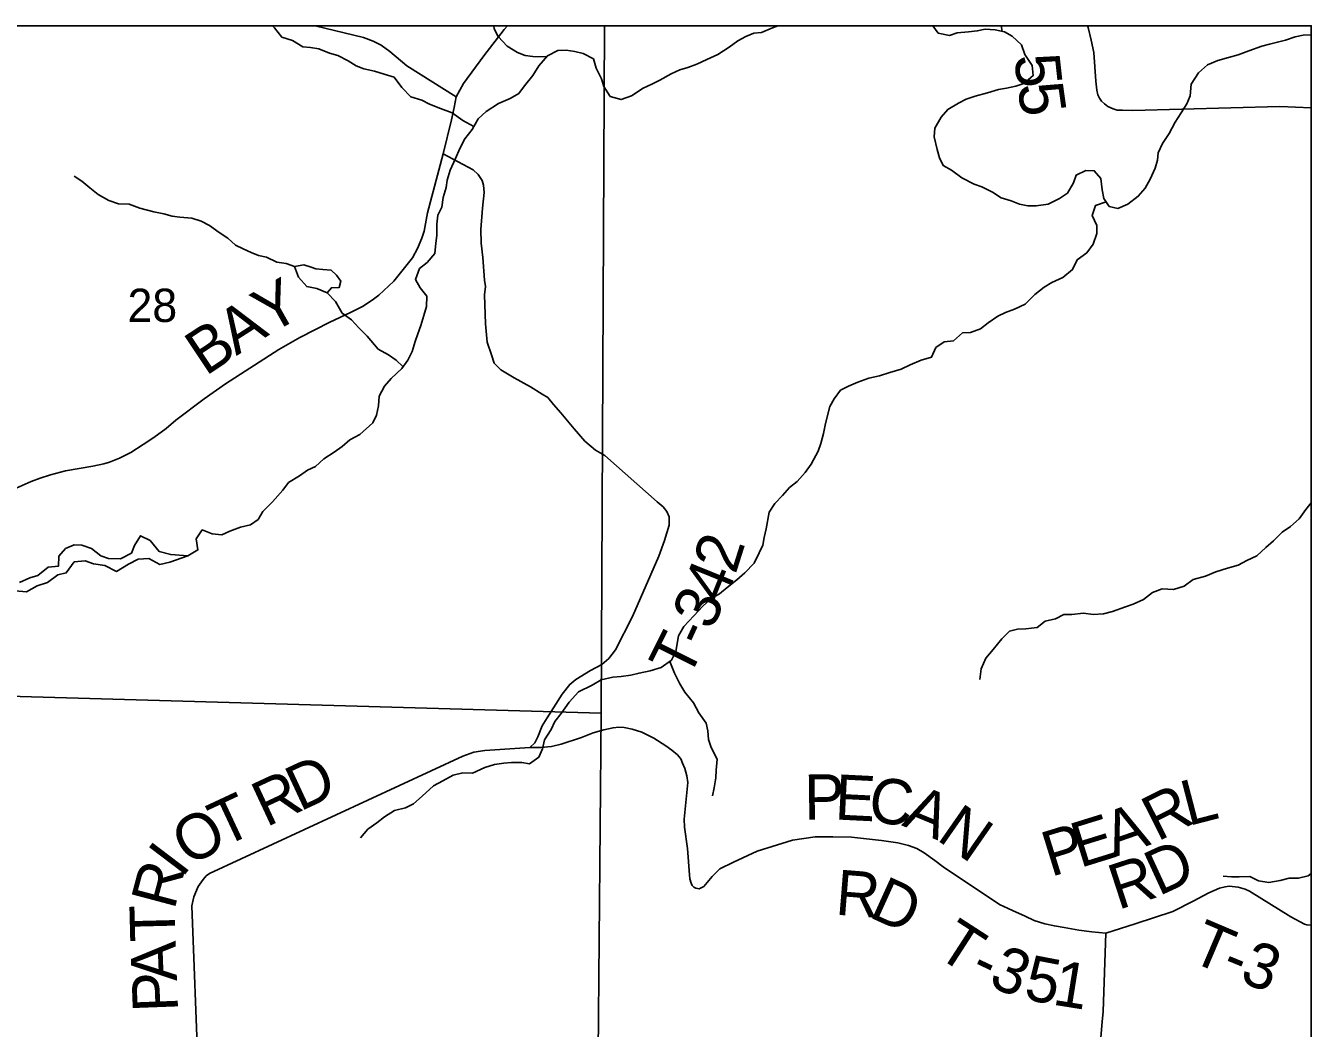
# Model space of a CAD drawing. Extents: x -3.6 to 34, y 0 to 32.8.
# Drawn here: x 1.556 to 3.17, y 31.583 to 32.843 of the extents above; entities that cross this region are included whole.
import ezdxf

# ---------------------------------------------------------------- set-up
doc = ezdxf.new("R2010")
doc.units = 0
for name, color, linetype in [('GM_X_Corporation', 7, 'Continuous'), ('GM_X_County_Road', 7, 'Continuous'), ('GM_X_County_Road_Text', 7, 'Continuous'), ('GM_X_Minor_Lake', 7, 'Continuous'), ('GM_X_Minor_River', 7, 'Continuous'), ('GM_X_Section_Text', 7, 'Continuous'), ('GM_X_Township_Road', 7, 'Continuous'), ('GM_X_Township_Road_Text', 7, 'Continuous'), ('SH_Data', 7, 'Continuous')]:
    doc.layers.add(name, color=color, linetype=linetype)

msp = doc.modelspace()

# ---------------------------------------------------------------- linework, layer by layer
at = {"layer": 'GM_X_Corporation'}
for points in [[(3.1705, 28.9337), (3.1705, 32.8429), (-3.6295, 32.8429), (-3.6295, 26.0429), (2.3706, 26.0429), (2.3712, 26.0804), (2.3716, 26.1248), (2.3732, 26.2253), (2.3789, 26.6097), (2.3911, 27.5117), (2.3952, 27.9336), (2.3997, 28.282), (2.4082, 28.9473), (2.5416, 28.945), (2.5837, 28.9442), (2.8343, 28.9397)], [(3.1705, 30.458), (3.1705, 32.8429), (-3.6295, 32.8429), (-3.6295, 30.6462), (-3.5736, 30.6453), (-2.8007, 30.6338), (-2.7027, 30.634), (-2.3541, 30.6318), (-0.5034, 30.5954), (-0.453, 30.5952), (-0.398, 30.5946), (0.2583, 30.5905), (0.2578, 30.5133), (0.3556, 30.5115), (0.4055, 30.5105), (1.2437, 30.4948), (1.7819, 30.4857), (3.0419, 30.4594)], [(2.2831, 32.8429), (1.2753, 32.8429), (1.2712, 32.0083), (2.2789, 31.9792)], [(1.2712, 32.0083), (2.2789, 31.9792), (2.27, 30.9827), (1.2573, 30.9978)]]:
    msp.add_lwpolyline(points, close=True, dxfattribs=at)
at = {"layer": 'GM_X_County_Road'}
for points in [[(2.1611, 32.8429), (2.1568, 32.838), (2.1315, 32.8052), (2.1059, 32.7701), (2.0966, 32.7534)], [(2.8896, 32.8429), (2.8904, 32.8407), (2.8942, 32.8247), (2.8974, 32.8092), (2.8998, 32.7732), (2.901, 32.7618), (2.9026, 32.7561), (2.9046, 32.7518), (2.9071, 32.7482), (2.9109, 32.7446), (2.9149, 32.7413), (2.9217, 32.7384), (2.9269, 32.7369), (2.9336, 32.7367), (2.9462, 32.7365), (3.131, 32.7413), (3.1705, 32.7399)], [(2.0966, 32.7534), (2.0942, 32.7401), (2.0908, 32.7247), (2.0803, 32.6821)], [(2.0803, 32.6821), (2.0608, 32.6079), (2.0565, 32.5846), (2.0534, 32.576), (2.048, 32.563), (2.042, 32.5513), (2.0185, 32.5219), (1.9995, 32.5042), (1.9914, 32.4979), (1.9792, 32.49), (1.9641, 32.4827), (1.9382, 32.4704), (1.9003, 32.4513), (1.8742, 32.4361), (1.8069, 32.3932), (1.7803, 32.3742), (1.7446, 32.3475), (1.7325, 32.3369), (1.717, 32.3258), (1.7036, 32.3168), (1.6883, 32.3069), (1.6738, 32.2996), (1.6613, 32.2946), (1.6541, 32.2927), (1.6404, 32.2895), (1.6061, 32.2836), (1.5875, 32.2786), (1.5744, 32.2745), (1.5629, 32.2702), (1.5368, 32.2588)]]:
    msp.add_lwpolyline(points, dxfattribs=at)
at = {"layer": 'GM_X_Minor_Lake'}
for points in [[(1.9349, 32.5073), (1.9401, 32.5138), (1.9496, 32.514), (1.9521, 32.522), (1.9463, 32.5295), (1.9397, 32.5358), (1.9295, 32.5368), (1.9204, 32.5374), (1.9146, 32.5396), (1.9055, 32.5425), (1.8937, 32.5404)], [(1.8937, 32.5404), (1.8989, 32.5272), (1.909, 32.5152), (1.9219, 32.5128), (1.9349, 32.5073)]]:
    msp.add_lwpolyline(points, dxfattribs=at)
at = {"layer": 'GM_X_Minor_River'}
msp.add_line((2.7817, 32.8361), (2.7814, 32.8429), dxfattribs=at)
for points in [[(1.7597, 32.177), (1.7725, 32.1844), (1.7704, 32.1984), (1.7778, 32.2095), (1.7904, 32.2048), (1.8026, 32.2035), (1.8124, 32.2078), (1.8259, 32.213), (1.8384, 32.2159), (1.8482, 32.2228), (1.8541, 32.2328), (1.866, 32.2448), (1.8791, 32.2594), (1.8861, 32.269), (1.9, 32.2776), (1.9102, 32.2846), (1.92, 32.2893), (1.9304, 32.2986), (1.9436, 32.3071), (1.9537, 32.3141), (1.9634, 32.3226), (1.9759, 32.3293), (1.9919, 32.344), (1.9967, 32.3535), (1.9992, 32.3653), (2.0001, 32.3775), (2.0067, 32.3901), (2.0149, 32.3997), (2.0284, 32.4121), (2.0362, 32.4228), (2.0413, 32.4335), (2.0453, 32.4461), (2.0485, 32.456), (2.0522, 32.4663), (2.0561, 32.4789), (2.0594, 32.49), (2.0599, 32.5033), (2.0517, 32.5138), (2.0455, 32.5239), (2.0506, 32.5377), (2.0603, 32.5454), (2.07, 32.5566), (2.0713, 32.5695), (2.0723, 32.5794), (2.0724, 32.5934), (2.0738, 32.6048), (2.0789, 32.6148), (2.0806, 32.6269), (2.0842, 32.6395), (2.0855, 32.649), (2.0891, 32.6612), (2.0957, 32.6761), (2.1012, 32.6887), (2.1078, 32.7006), (2.1168, 32.7125), (2.1245, 32.7259), (2.1342, 32.7352), (2.15, 32.7453), (2.1647, 32.7516), (2.1756, 32.7579), (2.1827, 32.7675), (2.1931, 32.7805), (2.2005, 32.7924), (2.2113, 32.8051), (2.2244, 32.8118), (2.2347, 32.8123), (2.2457, 32.8106), (2.256, 32.8081), (2.269, 32.8011), (2.2727, 32.7894), (2.2793, 32.7762), (2.2822, 32.7664), (2.2903, 32.754), (2.3037, 32.7501), (2.3169, 32.7549), (2.3315, 32.7642), (2.3425, 32.7693), (2.3523, 32.7744), (2.3666, 32.7822), (2.3775, 32.7873), (2.3877, 32.7902), (2.399, 32.7945), (2.4114, 32.8004), (2.4254, 32.8067), (2.4397, 32.8157), (2.4502, 32.8238), (2.4603, 32.8293), (2.4705, 32.8336), (2.48, 32.8345), (2.4939, 32.8401), (2.5008, 32.8429)], [(2.1189, 32.7162), (2.1052, 32.7237), (2.0917, 32.7333), (2.0772, 32.7388), (2.0634, 32.7443), (2.0535, 32.7494), (2.0398, 32.7534), (2.0285, 32.7653), (2.0188, 32.7784), (2.0062, 32.782), (1.994, 32.7856), (1.9807, 32.7888), (1.9711, 32.7925), (1.9612, 32.7988), (1.9481, 32.8054), (1.9375, 32.8082), (1.9241, 32.8137), (1.9138, 32.8154), (1.9043, 32.8164), (1.8912, 32.8242), (1.8779, 32.8285), (1.8686, 32.8401), (1.8659, 32.8429)], [(2.21, 32.8036), (2.1931, 32.8041), (2.1832, 32.8054), (2.1736, 32.8091), (2.1606, 32.8172), (2.1494, 32.8291), (2.1446, 32.8389), (2.1439, 32.8429)], [(2.6952, 32.8429), (2.7021, 32.8336), (2.7162, 32.8304), (2.726, 32.834), (2.74, 32.8353), (2.751, 32.8363), (2.7609, 32.8383), (2.7734, 32.8378), (2.7852, 32.8353), (2.7948, 32.8298), (2.8068, 32.819), (2.8108, 32.8065), (2.8201, 32.793), (2.8211, 32.7801), (2.8095, 32.7701), (2.7993, 32.7669), (2.7879, 32.7644), (2.7777, 32.7627), (2.7641, 32.7587), (2.7486, 32.7543), (2.7373, 32.7507), (2.7275, 32.7456), (2.714, 32.7378), (2.7058, 32.7278), (2.6976, 32.714), (2.6971, 32.7033), (2.7007, 32.6875), (2.7036, 32.6769), (2.7083, 32.6671), (2.7187, 32.6612), (2.7317, 32.6519), (2.747, 32.6438), (2.7566, 32.6406), (2.77, 32.6336), (2.7811, 32.6265), (2.7937, 32.623), (2.804, 32.6186), (2.8147, 32.6168), (2.825, 32.6166), (2.8401, 32.6188), (2.8544, 32.6258), (2.8642, 32.6324), (2.8719, 32.6455), (2.8752, 32.655), (2.8872, 32.6609), (2.8979, 32.6607), (2.906, 32.651), (2.9078, 32.6366), (2.9098, 32.626), (2.9168, 32.6159), (2.9275, 32.6134), (2.9403, 32.6185), (2.9531, 32.6286), (2.962, 32.6386), (2.9683, 32.6501), (2.9745, 32.6638), (2.9774, 32.6738), (2.9784, 32.6833), (2.9835, 32.6947), (2.992, 32.7074), (2.9994, 32.7215), (3.0071, 32.7334), (3.0142, 32.7449), (3.0182, 32.7549), (3.0198, 32.7693), (3.0287, 32.7835), (3.0403, 32.7935), (3.0531, 32.7991), (3.0667, 32.8031), (3.0788, 32.8063), (3.092, 32.8111), (3.1083, 32.817), (3.1181, 32.8195), (3.1279, 32.8223), (3.1381, 32.8247), (3.1502, 32.8287), (3.1604, 32.8308), (3.1705, 32.8313)], [(2.0302, 32.4145), (2.0214, 32.4226), (2.0118, 32.4296), (1.9987, 32.4366), (1.9848, 32.4527), (1.9744, 32.4632), (1.9655, 32.4733), (1.9536, 32.4818), (1.9453, 32.4965), (1.9349, 32.5073), (1.9219, 32.5128), (1.909, 32.5152), (1.8989, 32.5272), (1.8937, 32.5404), (1.8834, 32.544), (1.8716, 32.5457), (1.8586, 32.5523), (1.8487, 32.5541), (1.8391, 32.5581), (1.8292, 32.5625), (1.8196, 32.5673), (1.81, 32.5758), (1.7992, 32.5832), (1.7869, 32.5918), (1.7766, 32.5973), (1.7647, 32.6013), (1.7499, 32.6022), (1.74, 32.6035), (1.7297, 32.6064), (1.7172, 32.6092), (1.6996, 32.6135), (1.6862, 32.6186), (1.6726, 32.6191), (1.6607, 32.6235), (1.6473, 32.6308), (1.6369, 32.639), (1.6265, 32.6475), (1.6169, 32.6538)], [(2.9127, 32.6218), (2.8994, 32.6171), (2.8954, 32.6045), (2.9013, 32.5917), (2.9011, 32.5818), (2.8964, 32.5685), (2.8886, 32.5577), (2.8766, 32.5488), (2.8707, 32.5366), (2.8584, 32.5265), (2.8448, 32.5202), (2.835, 32.5144), (2.8234, 32.5051), (2.8111, 32.4931), (2.7979, 32.4868), (2.7866, 32.4825), (2.7768, 32.4781), (2.7648, 32.4696), (2.755, 32.4622), (2.7426, 32.4575), (2.7327, 32.4569), (2.7211, 32.4469), (2.7094, 32.4459), (2.6992, 32.4385), (2.6937, 32.4267), (2.6805, 32.4227), (2.6666, 32.4168), (2.6556, 32.4113), (2.6413, 32.4072), (2.6281, 32.4029), (2.6148, 32.4), (2.6009, 32.3952), (2.5892, 32.3901), (2.5794, 32.385), (2.5712, 32.3742), (2.5661, 32.3647), (2.5625, 32.3517), (2.56, 32.341), (2.5579, 32.3308), (2.5547, 32.3182), (2.5511, 32.3083), (2.5426, 32.2922), (2.5348, 32.2818), (2.5251, 32.2703), (2.5154, 32.2629), (2.5064, 32.2529), (2.4967, 32.2425), (2.4897, 32.2318), (2.4859, 32.2108), (2.4834, 32.1998), (2.4817, 32.1903), (2.4773, 32.1807), (2.471, 32.1677), (2.4591, 32.1554), (2.4493, 32.1469), (2.437, 32.1372), (2.4272, 32.1291), (2.4171, 32.1232), (2.4066, 32.1136), (2.3951, 32.1016), (2.3827, 32.0881), (2.3761, 32.0766), (2.3726, 32.0569), (2.3671, 32.0458), (2.354, 32.0365), (2.3404, 32.0324), (2.3264, 32.0296), (2.3162, 32.0271), (2.3041, 32.0254), (2.2935, 32.0245), (2.2787, 32.0212), (2.2674, 32.0146), (2.2505, 32.0063), (2.2385, 31.9932), (2.2285, 31.979), (2.2207, 31.969), (2.216, 31.9587), (2.2078, 31.9457), (2.205, 31.9346), (2.2006, 31.9239), (2.189, 31.9158), (2.1791, 31.9175), (2.1662, 31.9173), (2.1567, 31.9164), (2.1449, 31.9147), (2.1328, 31.9111), (2.1174, 31.904), (2.1052, 31.9045), (2.0931, 31.9013), (2.08, 31.8943), (2.0683, 31.888), (2.0541, 31.8749), (2.0432, 31.8656), (2.0331, 31.8605), (2.0191, 31.8569), (2.0067, 31.8491), (1.9969, 31.8417), (1.9857, 31.8335), (1.9764, 31.8228)], [(3.1705, 32.2436), (3.1636, 32.2351), (3.1554, 32.2236), (3.1442, 32.2136), (3.1337, 32.2066), (3.1232, 32.1958), (3.1135, 32.1876), (3.1019, 32.1768), (3.0895, 32.1709), (3.0786, 32.1654), (3.0653, 32.1614), (3.0506, 32.157), (3.0378, 32.1515), (3.0223, 32.1471), (3.011, 32.1389), (2.9974, 32.1345), (2.9834, 32.1354), (2.9709, 32.1311), (2.9597, 32.1221), (2.9469, 32.1163), (2.9371, 32.1127), (2.9208, 32.1071), (2.9095, 32.1043), (2.8966, 32.1033), (2.8844, 32.105), (2.87, 32.1032), (2.8598, 32.1031), (2.8492, 32.098), (2.8364, 32.0951), (2.8262, 32.087), (2.8122, 32.0852), (2.8016, 32.0847), (2.7914, 32.0822), (2.7817, 32.0726), (2.7709, 32.0591), (2.762, 32.0484), (2.7561, 32.035), (2.7544, 32.0217)], [(1.7597, 32.177), (1.7384, 32.1785), (1.7236, 32.1825), (1.7123, 32.1963), (1.7004, 32.2022), (1.6927, 32.1899), (1.689, 32.1804), (1.6751, 32.1733), (1.6603, 32.1735), (1.6507, 32.1771), (1.6388, 32.186), (1.6266, 32.1904), (1.6171, 32.1906), (1.6062, 32.1862), (1.598, 32.1766), (1.5974, 32.1641), (1.5845, 32.1627), (1.5714, 32.1523), (1.5612, 32.1494), (1.5484, 32.1435)], [(1.5429, 32.1332), (1.557, 32.1319), (1.5705, 32.1393), (1.5837, 32.1434), (1.5965, 32.1531), (1.6071, 32.1555), (1.6171, 32.1693), (1.6307, 32.1707), (1.6414, 32.1671), (1.6555, 32.165), (1.6704, 32.1573), (1.6851, 32.1667), (1.6975, 32.1729), (1.7108, 32.1735), (1.7246, 32.1662), (1.7371, 32.169), (1.7597, 32.177)], [(2.3651, 32.0443), (2.3708, 32.0295), (2.3775, 32.016), (2.3838, 32.0058), (2.3946, 31.9923), (2.4016, 31.9799), (2.4106, 31.9668), (2.4127, 31.957), (2.4136, 31.9464), (2.4168, 31.9362), (2.4246, 31.9215), (2.4234, 31.9078), (2.4228, 31.8979), (2.4207, 31.8854), (2.4186, 31.8755)], [(3.1705, 31.7778), (3.1667, 31.7749), (3.1546, 31.7721), (3.1429, 31.7719), (3.1315, 31.7691), (3.1171, 31.7665), (3.1042, 31.7686), (3.0931, 31.7741), (3.0798, 31.7739), (3.0703, 31.7737), (3.0597, 31.7747)]]:
    msp.add_lwpolyline(points, dxfattribs=at)
at = {"layer": 'GM_X_Township_Road'}
for points in [[(1.9196, 32.8429), (1.9803, 32.8282), (1.9923, 32.8236), (2.0026, 32.8182), (2.0135, 32.8104), (2.0348, 32.7926), (2.0966, 32.7534)], [(2.0966, 32.7534), (2.0942, 32.7401), (2.0908, 32.7247), (2.0803, 32.6821)], [(2.0803, 32.6821), (2.118, 32.6617), (2.1245, 32.656), (2.1268, 32.6523), (2.1292, 32.6485), (2.1311, 32.6424), (2.1318, 32.6332), (2.1296, 32.6137), (2.1276, 32.5868), (2.128, 32.5696), (2.13, 32.5515), (2.1325, 32.5232), (2.1334, 32.5152), (2.1321, 32.5049), (2.1335, 32.4684), (2.1357, 32.4455), (2.141, 32.4295), (2.1444, 32.4189), (2.1526, 32.4107), (2.1695, 32.4005), (2.1902, 32.3893), (2.2046, 32.3802), (2.2118, 32.3759), (2.2189, 32.3672), (2.228, 32.3564), (2.2449, 32.3365), (2.2584, 32.3212), (2.2718, 32.3095), (2.2833, 32.3029), (2.3489, 32.2447), (2.3565, 32.2383), (2.3614, 32.2325), (2.3643, 32.2261), (2.3643, 32.2153), (2.3584, 32.1964), (2.3513, 32.1767), (2.318, 32.1006), (2.2968, 32.0587), (2.2884, 32.0479), (2.2798, 32.0406), (2.2656, 32.0328), (2.2469, 32.0216), (2.2394, 32.0154), (2.2298, 32.0034), (2.211, 31.9733), (2.2046, 31.9633), (2.1992, 31.9498), (2.1954, 31.9421), (2.1894, 31.9363), (2.1326, 31.9325), (2.1187, 31.9302), (2.1052, 31.9252), (1.7871, 31.778), (1.783, 31.7749), (1.7789, 31.7706), (1.7726, 31.7617), (1.7672, 31.7487), (1.7647, 31.7372), (1.7726, 31.5296)], [(2.9126, 31.7028), (2.8951, 31.7045), (2.8785, 31.7069), (2.86, 31.7102), (2.848, 31.7121), (2.8358, 31.7149), (2.8227, 31.7188), (2.8112, 31.7244), (2.7954, 31.7314), (2.7791, 31.7389), (2.7082, 31.7862), (2.6977, 31.7944), (2.6843, 31.804), (2.6753, 31.8092), (2.6649, 31.8133), (2.6512, 31.8164), (2.6306, 31.8194), (2.5933, 31.8234), (2.5696, 31.8241), (2.5476, 31.824), (2.5191, 31.8196), (2.4748, 31.8058), (2.445, 31.792), (2.4277, 31.7836), (2.418, 31.774), (2.4076, 31.7616), (2.4052, 31.7602), (2.402, 31.7586), (2.3978, 31.7595), (2.3951, 31.7608), (2.3931, 31.7627), (2.3917, 31.7657), (2.3903, 31.7712), (2.3895, 31.7763), (2.3871, 31.8095), (2.3833, 31.8362), (2.383, 31.8461), (2.3877, 31.8922), (2.3862, 31.9005), (2.3839, 31.91), (2.381, 31.9165), (2.3788, 31.9219), (2.3745, 31.9271), (2.3676, 31.933), (2.3602, 31.9384), (2.3451, 31.948), (2.3298, 31.9554), (2.3179, 31.9594), (2.3075, 31.9613), (2.3009, 31.9617), (2.2937, 31.9611), (2.2822, 31.9584), (2.2687, 31.9546), (2.254, 31.9487), (2.2287, 31.9405), (2.2166, 31.9375), (2.203, 31.9361), (2.1894, 31.9363)], [(2.9126, 31.7028), (2.9494, 31.7147), (2.9967, 31.7301), (3.0223, 31.7431), (3.0419, 31.7538), (3.0551, 31.7594), (3.0623, 31.7613), (3.0673, 31.7619), (3.0787, 31.7606), (3.0873, 31.7584), (3.0929, 31.7559), (3.1449, 31.7235), (3.1619, 31.7143), (3.1649, 31.7135), (3.1698, 31.7132), (3.1705, 31.7133)], [(2.9079, 31.5917), (2.9091, 31.6046), (2.9126, 31.7028)], [(2.9153, 31.4922), (2.9057, 31.5425), (2.9049, 31.5569), (2.9079, 31.5917)]]:
    msp.add_lwpolyline(points, dxfattribs=at)
at = {"layer": 'SH_Data'}
for p, q in [((-3.6295, 32.8429), (3.1705, 32.8429)), ((3.1705, 32.8429), (3.1705, 26.0429))]:
    msp.add_line(p, q, dxfattribs=at)

# ---------------------------------------------------------------- texts
at = {"layer": 'GM_X_County_Road_Text'}
for s, rotation, p in [('5', 276.2678, (2.7974, 32.8049)), ('5', 277.9482, (2.8015, 32.7683)), ('Y', 29.4008, (1.8621, 32.4542)), ('A', 32.5089, (1.8206, 32.4278)), ('B', 33.624, (1.782, 32.4021))]:
    msp.add_text(s, height=0.0568, rotation=rotation, dxfattribs=at).set_placement(p)
at = {"layer": 'GM_X_Section_Text'}
msp.add_text('28', height=0.04186, rotation=0, dxfattribs=at).set_placement((1.6841, 32.4707))
at = {"layer": 'GM_X_Township_Road_Text'}
for s, rotation, p in [('2', 72.4378, (2.4474, 32.1527)), ('4', 67.9867, (2.4326, 32.1157)), ('3', 66.2564, (2.4178, 32.082)), ('T', 63.4771, (2.3878, 32.02)), ('-', 65.3742, (2.4077, 32.0599)), ('D', 24.981, (1.9005, 31.8554)), ('R', 24.9797, (1.8582, 31.8357)), ('P', 0.7103, (2.534, 31.8454)), ('E', 357.1575, (2.5714, 31.8459)), ('C', 352.2447, (2.6125, 31.8439)), ('A', 337.6108, (2.6551, 31.8386)), ('R', 26.7247, (2.9773, 31.8176)), ('L', 14.556, (3.016, 31.8374)), ('T', 25.0201, (1.8038, 31.8103)), ('O', 30.4208, (1.7619, 31.7857)), ('N', 325.2041, (2.6985, 31.8211)), ('E', 17.2226, (2.88, 31.7847)), ('A', 19.1856, (2.9226, 31.798)), ('P', 17.2231, (2.8434, 31.7734)), ('I', 52.8179, (1.7522, 31.771)), ('D', 24.7431, (2.9788, 31.7491)), ('R', 75.099, (1.7427, 31.7311)), ('R', 18.0474, (2.9278, 31.732)), ('R', 355.4091, (2.5719, 31.7264)), ('D', 335.6266, (2.6134, 31.724)), ('T', 91.423, (1.7443, 31.6928)), ('T', 327.1396, (2.697, 31.6758)), ('T', 336.9753, (3.0155, 31.6691)), ('A', 92.1643, (1.7462, 31.6431)), ('3', 339.5586, (3.0788, 31.6425)), ('3', 337.2544, (2.7634, 31.6376)), ('5', 349.1487, (2.808, 31.6204)), ('-', 337.6362, (3.0553, 31.6522)), ('-', 334.6511, (2.7398, 31.6488)), ('1', 350.8559, (2.8442, 31.6135)), ('P', 92.1767, (1.7476, 31.6048))]:
    msp.add_text(s, height=0.0568, rotation=rotation, dxfattribs=at).set_placement(p)

doc.saveas('drawing.dxf')
